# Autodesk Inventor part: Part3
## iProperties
Created: 2002-02
Part Number: Part3
Document SubType Name: ﾓﾃﾞﾘﾝｸﾞ
Designer: Administrator
Control State: 0
Master: False
Checked Out: False
Shininess: 64.0
Length Units: 11269
Angle Units: 11279
Time Units: 11290
Mass Units: 11284
Length Display Precision: 2
Angle Display Precision: 1
Density: 0.0
Volumn: 0.0
Area: 0.0
PropertySet Name: Model Information
Author: Administrator
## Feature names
1. 押し出し1 [Extrusion]
2. 押し出し2 [Extrusion]
3. 押し出し3 [Extrusion]
4. 押し出し4 [Extrusion]
5. 面取り1 [Chamfer]
